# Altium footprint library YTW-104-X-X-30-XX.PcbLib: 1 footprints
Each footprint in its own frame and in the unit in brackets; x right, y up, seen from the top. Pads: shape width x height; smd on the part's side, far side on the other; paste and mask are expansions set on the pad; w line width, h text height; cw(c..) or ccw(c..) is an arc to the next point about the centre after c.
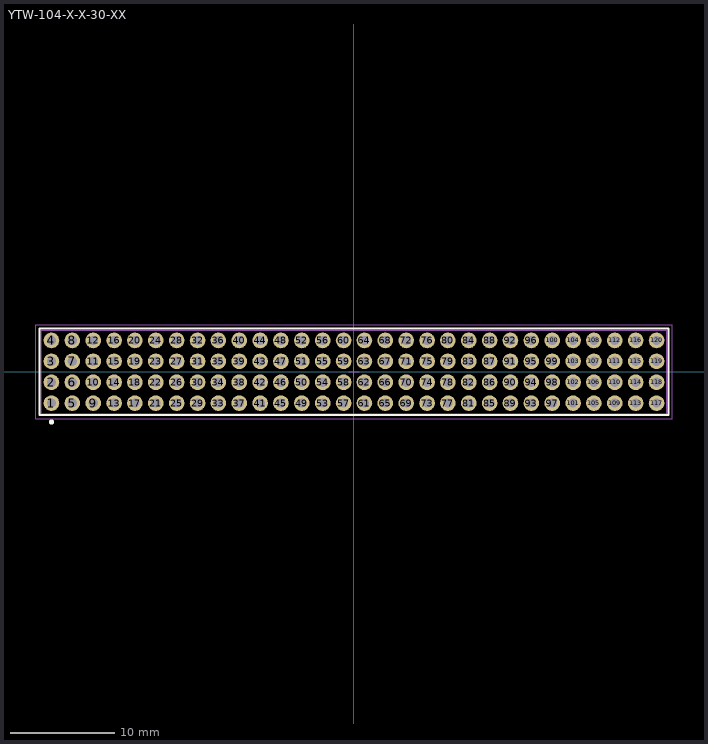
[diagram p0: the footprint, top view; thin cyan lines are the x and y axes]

## YTW-104-X-X-30-XX [mm] "2.00mm pitch, 120 pin, stacker; 4 rows"
height 3.05
pads (120):
  round 1.5 hole 0.89 mask+0: 1(-29,-3) 2(-29,-1) 3(-29,1) 4(-29,3) 5(-27,-3) 6(-27,-1) 7(-27,1) 8(-27,3) 9(-25,-3) 10(-25,-1) 11(-25,1) 12(-25,3) 13(-23,-3) 14(-23,-1) 15(-23,1) 16(-23,3) 17(-21,-3) 18(-21,-1) 19(-21,1) 20(-21,3) 21(-19,-3) 22(-19,-1) 23(-19,1) 24(-19,3) 25(-17,-3) 26(-17,-1) 27(-17,1) 28(-17,3) 29(-15,-3) 30(-15,-1) 31(-15,1) 32(-15,3) 33(-13,-3) 34(-13,-1) 35(-13,1) 36(-13,3) 37(-11,-3) 38(-11,-1) 39(-11,1) 40(-11,3) 41(-9,-3) 42(-9,-1) 43(-9,1) 44(-9,3) 45(-7,-3) 46(-7,-1) 47(-7,1) 48(-7,3) 49(-5,-3) 50(-5,-1) 51(-5,1) 52(-5,3) 53(-3,-3) 54(-3,-1) 55(-3,1) 56(-3,3) 57(-1,-3) 58(-1,-1) 59(-1,1) 60(-1,3) 61(1,-3) 62(1,-1) 63(1,1) 64(1,3) 65(3,-3) 66(3,-1) 67(3,1) 68(3,3) 69(5,-3) 70(5,-1) 71(5,1) 72(5,3) 73(7,-3) 74(7,-1) 75(7,1) 76(7,3) 77(9,-3) 78(9,-1) 79(9,1) 80(9,3) 81(11,-3) 82(11,-1) 83(11,1) 84(11,3) 85(13,-3) 86(13,-1) 87(13,1) 88(13,3) 89(15,-3) 90(15,-1) 91(15,1) 92(15,3) 93(17,-3) 94(17,-1) 95(17,1) 96(17,3) 97(19,-3) 98(19,-1) 99(19,1) 100(19,3) 101(21,-3) 102(21,-1) 103(21,1) 104(21,3) 105(23,-3) 106(23,-1) 107(23,1) 108(23,3) 109(25,-3) 110(25,-1) 111(25,1) 112(25,3) 113(27,-3) 114(27,-1) 115(27,1) 116(27,3) 117(29,-3) 118(29,-1) 119(29,1) 120(29,3)
Top Overlay:
  circle w0.25: c-29,-4.8 r0.125
  lines w0.2: -30.15,-4.15 30.15,-4.15 30.15,4.15 -30.15,4.15 -30.15,-4.15
Mechanical 12:
  lines w0.001: -30,-4 30,-4 30,4 -30,4 -30,-4
Mechanical 13:
  lines w0.1: -30,-4 30,-4 30,4 -30,4 -30,-4
  text ".Designator" at 0,0 h1.52
Mechanical 15:
  lines w0.05: -29.5,-3 -28.5,-3 ; -29,-3.5 -29,-2.5 ; -0.5,0 0.5,0 ; 0,-0.5 0,0.5 ; -30.5,-4.5 30.5,-4.5 30.5,4.5 -30.5,4.5 -30.5,-4.5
